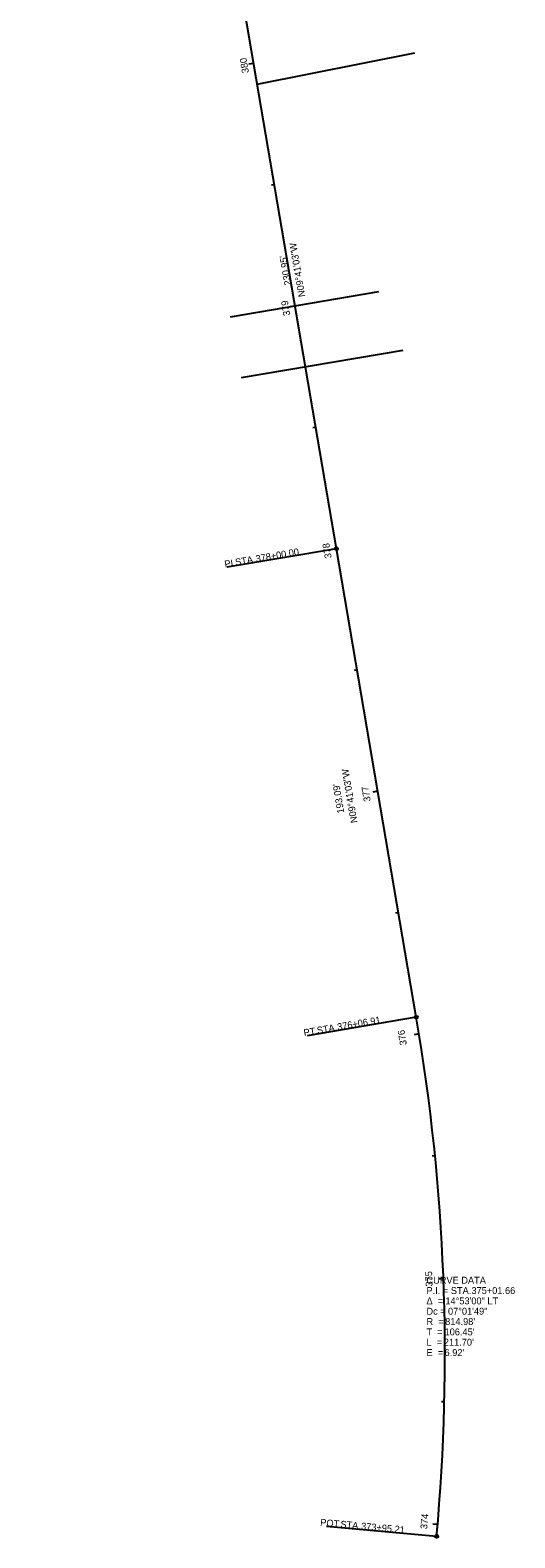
# Model space of a CAD drawing. Extents: x 111442 to 112326, y 429427 to 431077.
# Drawn here: x 112129 to 112326, y 429427 to 430040 of the extents above; entities that cross this region are included whole.
import ezdxf

# ---------------------------------------------------------------- set-up
doc = ezdxf.new("R2010")
doc.units = 0
for name, color, linetype in [('GE_P_Alignment', 7, 'Continuous'), ('GE_P_Alignment_100_Bearings', 7, 'Continuous'), ('GE_P_Alignment_100_Cardinal_Points', 7, 'Continuous'), ('GE_P_Alignment_100_Curve_Data', 7, 'Continuous'), ('GE_P_Alignment_100_Distances', 7, 'Continuous'), ('GE_P_Alignment_100_Stations', 7, 'Continuous'), ('SC_Scratch10', 7, 'Continuous'), ('SC_Scratch4', 7, 'Continuous')]:
    doc.layers.add(name, color=color, linetype=linetype)

msp = doc.modelspace()

# ---------------------------------------------------------------- linework, layer by layer
at = {"layer": 'GE_P_Alignment'}
for p, q in [((112253.32, 429829.29), (112128.86, 430558.62)), ((112253.32, 429829.29), (112214.47, 430056.95)), ((112285.8, 429638.95), (112253.32, 429829.29))]:
    msp.add_line(p, q, dxfattribs=at)
msp.add_arc((111482.43, 429501.86), 814.98, 354.80081, 9.68423, dxfattribs=at)
at = {"layer": 'GE_P_Alignment_100_Cardinal_Points'}
for p, q in [((112253.32, 429829.29), (112208.96, 429821.72)), ((112285.8, 429638.95), (112241.45, 429631.39)), ((112294.06, 429428.01), (112249.25, 429432.08))]:
    msp.add_line(p, q, dxfattribs=at)
for centre in [(112253.32, 429829.29), (112285.8, 429638.95), (112294.06, 429428.01)]:
    msp.add_circle(centre, 0.6, dxfattribs=at)
at = {"layer": 'GE_P_Alignment_100_Stations'}
for p, q in [((112219.68, 430026.44), (112217.71, 430026.11)), ((112228.09, 429977.16), (112226.91, 429976.95)), ((112236.5, 429927.87), (112234.53, 429927.53)), ((112244.91, 429878.58), (112243.73, 429878.38)), ((112253.32, 429829.29), (112251.35, 429828.96)), ((112261.73, 429780.01), (112260.55, 429779.8)), ((112270.14, 429730.72), (112268.17, 429730.38)), ((112278.56, 429681.43), (112277.37, 429681.23)), ((112286.94, 429632.14), (112284.96, 429631.82)), ((112293.41, 429582.57), (112292.22, 429582.45)), ((112296.83, 429532.69), (112294.84, 429532.62)), ((112297.19, 429482.7), (112295.99, 429482.73)), ((112294.49, 429432.78), (112292.49, 429432.95))]:
    msp.add_line(p, q, dxfattribs=at)
at = {"layer": 'SC_Scratch10'}
msp.add_line((112270.4, 429933.65), (112210.12, 429923.36), dxfattribs=at)
msp.add_lwpolyline([(112236.5, 429927.87), (112236.5, 429927.87)], close=True, dxfattribs=at)
at = {"layer": 'SC_Scratch4'}
for p, q in [((112221.12, 430018.01), (112285.26, 430030.71)), ((112214.79, 429898.8), (112280.44, 429910))]:
    msp.add_line(p, q, dxfattribs=at)

# ---------------------------------------------------------------- texts
at = {"layer": 'GE_P_Alignment_100_Bearings'}
for p in [(112240.7, 429931.79), (112261.94, 429718.07)]:
    msp.add_text('N09°41\'03"W', height=2.8, rotation=99.68414, dxfattribs=at).set_placement(p)
at = {"layer": 'GE_P_Alignment_100_Cardinal_Points'}
for s, rotation, p in [('378+00.00', 9.68414, (112220.74, 429823.77)), ('PI', 9.68414, (112208.08, 429821.61)), (' STA. ', 9.68414, (112211.42, 429822.19)), ('376+06.91', 9.68414, (112253.91, 429633.56)), ('PT', 9.68414, (112240.25, 429631.22)), (' STA. ', 9.68414, (112244.6, 429631.97)), ('POT', 354.80081, (112246.66, 429432.36)), (' STA. ', 354.80081, (112253.83, 429431.71)), ('373+95.21', 354.80081, (112263.25, 429430.85))]:
    msp.add_text(s, height=2.8, rotation=rotation, dxfattribs=at).set_placement(p)
at = {"layer": 'GE_P_Alignment_100_Curve_Data'}
for s, p in [('CURVE DATA', (112289.93, 429530.68)), ('P.I. = STA. ', (112289.93, 429526.48)), ('375+01.66', (112308.2, 429526.48)), ('Δ  = ', (112289.93, 429522.28)), ('14°53\'00" LT', (112297.61, 429522.28)), ('Dc = ', (112289.93, 429518.08)), ('R  = ', (112289.93, 429513.88)), ("814.98'", (112297.52, 429513.88)), ('07°01\'49"', (112298.67, 429518.08)), ('T  = ', (112289.93, 429509.68)), ("106.45'", (112297.27, 429509.68)), ('L  = ', (112289.93, 429505.48)), ('E  = ', (112289.93, 429501.28)), ("211.70'", (112296.98, 429505.48)), ("6.92'", (112297.27, 429501.28))]:
    msp.add_text(s, height=2.8, dxfattribs=at).set_placement(p)
at = {"layer": 'GE_P_Alignment_100_Distances'}
for s, p in [("230.95'", (112234.98, 429936.53)), ("193.09'", (112256.56, 429722))]:
    msp.add_text(s, height=2.8, rotation=99.68414, dxfattribs=at).set_placement(p)
at = {"layer": 'GE_P_Alignment_100_Stations'}
for s, rotation, p in [('380', 99.68414, (112217.78, 430022.72)), ('379', 99.68414, (112234.6, 429924.18)), ('378', 99.68414, (112251.42, 429825.59)), ('377', 99.68414, (112267.29, 429726.76)), ('376', 99.19844, (112281.95, 429627.77)), ('375', 92.16815, (112292.42, 429529.57)), ('374', 85.13785, (112290.21, 429430.85))]:
    msp.add_text(s, height=2.8, rotation=rotation, dxfattribs=at).set_placement(p)

doc.saveas('drawing.dxf')
